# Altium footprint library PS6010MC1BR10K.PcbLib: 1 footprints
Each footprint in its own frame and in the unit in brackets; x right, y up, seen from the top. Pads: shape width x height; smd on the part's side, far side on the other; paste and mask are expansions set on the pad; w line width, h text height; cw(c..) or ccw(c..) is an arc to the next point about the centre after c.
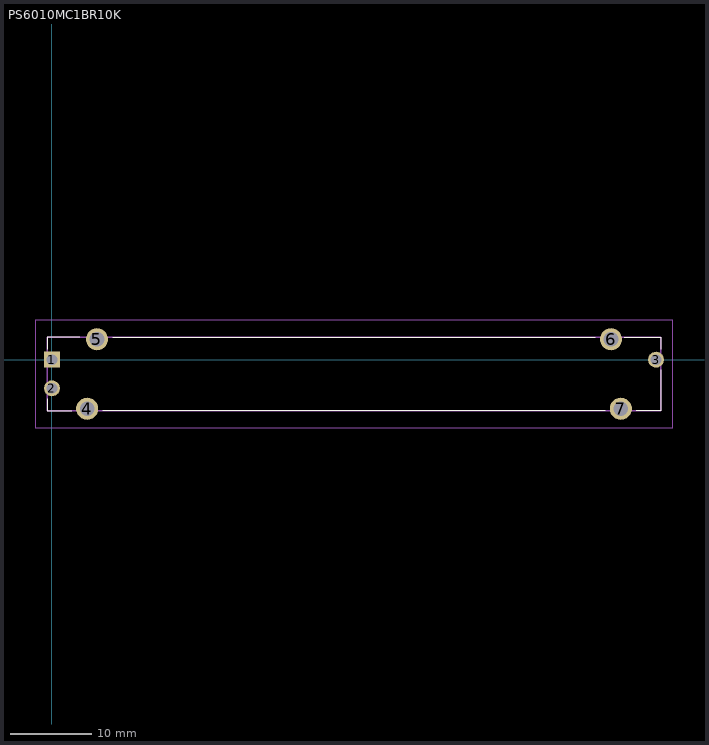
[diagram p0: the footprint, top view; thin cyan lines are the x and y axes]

## PS6010MC1BR10K [mm]
pads (7):
  rect 1.95x1.95 hole 1.3: 1(0,0)
  round 1.95 hole 1.3: 2(0,-3.5) 3(73.8,0)
  round 2.7 hole 1.8: 4(4.3,-6) 5(5.5,2.5) 6(68.3,2.5) 7(69.5,-6)
Top Overlay:
  lines w0.1: -0.6,-4.75 -0.6,-6.25 2.4,-6.25 ; -0.6,1.25 -0.6,2.75 3.4,2.75 ; 6.2,-6.25 67.6,-6.25 ; 7.4,2.75 66.4,2.75 ; 69.9,2.75 74.4,2.75 74.4,1.25 ; 71.4,-6.25 74.4,-6.25 74.4,-1.25
Mechanical 15:
  lines w0.2: -0.6,-6.25 74.4,-6.25 74.4,2.75 -0.6,2.75 -0.6,-6.25
Mechanical 20:
  lines w0.1: -1.975,-8.35 75.775,-8.35 75.775,4.85 -1.975,4.85 -1.975,-8.35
